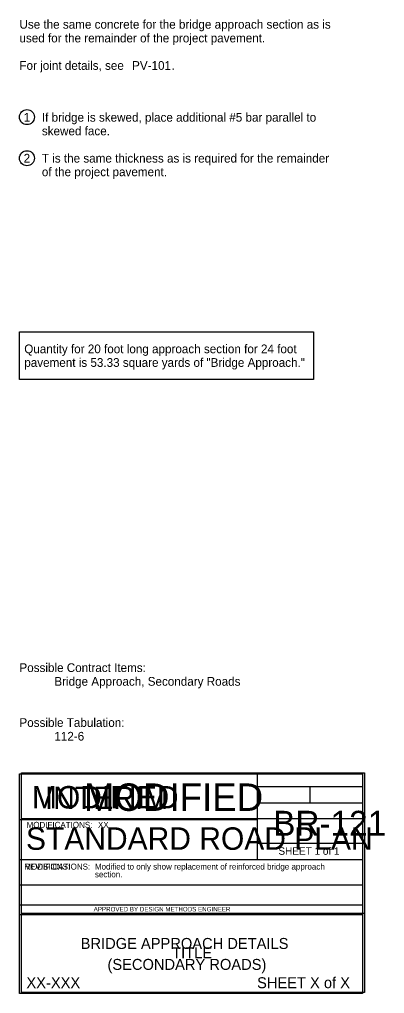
# Model space of a CAD drawing. Extents: x -2134222 to -2124595, y -2139046 to -2134021.
# Drawn here: x -2132487 to -2131755, y -2139046 to -2137094 of the extents above; entities that cross this region are included whole.
import ezdxf

# ---------------------------------------------------------------- set-up
doc = ezdxf.new("R2010")
doc.units = 0
for name, color, linetype in [('Barrier', 7, 'Continuous'), ('BridgeSuperStructureExisting', 7, 'Continuous'), ('Dimension', 7, 'Continuous'), ('dsnAlignmentCurveData', 7, 'Continuous'), ('dsnAlignmentTic', 7, 'Continuous'), ('DsnShtInsideBorder', 7, 'Continuous'), ('DsnShtPlotIdentification', 7, 'Continuous'), ('dsnStdLabel', 7, 'Continuous')]:
    doc.layers.add(name, color=color, linetype=linetype)

msp = doc.modelspace()

# ---------------------------------------------------------------- linework, layer by layer
at = {"layer": 'BridgeSuperStructureExisting'}
msp.add_lwpolyline([(-2132487.5, -2137719.6), (-2131897.5, -2137719.6), (-2131897.5, -2137815.6), (-2132487.5, -2137815.6)], close=True, dxfattribs=at)
for centre in [(-2132472.5, -2137289.5), (-2132472.5, -2137371.8)]:
    msp.add_circle(centre, 15, dxfattribs=at)
at = {"layer": 'Dimension'}
for p, q in [((-2132010.4, -2138605.9), (-2132010.4, -2138697.3)), ((-2132010.4, -2138630.9), (-2131799.4, -2138630.9)), ((-2131904.9, -2138630.9), (-2131904.9, -2138664.1)), ((-2132010.4, -2138664.1), (-2131799.4, -2138664.1)), ((-2132487.5, -2138697.3), (-2132010.4, -2138697.3)), ((-2132010.4, -2138697.3), (-2132010.4, -2138777.3)), ((-2131799.4, -2138745.1), (-2132010.4, -2138745.1)), ((-2132487.5, -2138777.3), (-2131799.4, -2138777.3)), ((-2132487.5, -2138828.3), (-2131799.4, -2138828.3)), ((-2132487.5, -2138868.3), (-2131799.4, -2138868.3)), ((-2132487.5, -2138887.3), (-2131799.4, -2138887.3))]:
    msp.add_line(p, q, dxfattribs=at)
msp.add_lwpolyline([(-2132487.5, -2138605.9), (-2131799.4, -2138605.9), (-2131799.4, -2139045.9), (-2132487.5, -2139045.9)], close=True, dxfattribs=at)
at = {"layer": 'DsnShtInsideBorder'}
for p, q in [((-2132483.1, -2138695), (-2131795.1, -2138695)), ((-2132483.1, -2138885), (-2131795.1, -2138885))]:
    msp.add_line(p, q, dxfattribs=at)
msp.add_lwpolyline([(-2132483.1, -2138603.7), (-2131795.1, -2138603.7), (-2131795.1, -2139043.7), (-2132483.1, -2139043.7)], close=True, dxfattribs=at)

# ---------------------------------------------------------------- texts
at = {"layer": 'Barrier'}
for s, p in [('1', (-2132479, -2137298.6)), ('If bridge is skewed, place additional #5 bar parallel to ', (-2132442.5, -2137298.6)), ('skewed face.', (-2132442.5, -2137325.9)), ('2', (-2132479, -2137380.6)), ('T is the same thickness as is required for the remainder ', (-2132442.5, -2137380.6)), ('of the project pavement.', (-2132442.5, -2137407.9))]:
    msp.add_text(s, height=17.5, dxfattribs=at).set_placement(p)
at = {"layer": 'Dimension'}
for s, height, p in [('BR-121', 50, (-2131978.5, -2138729.8)), ('STANDARD ROAD PLAN', 45.001, (-2132474.4, -2138757.9)), ('SHEET 1 of 1', 15, (-2131968, -2138767.9)), ('Modified to only show replacement of reinforced bridge approach ', 12, (-2132336.1, -2138797.5)), ('section.', 12, (-2132336.1, -2138813.1)), ('APPROVED BY DESIGN METHODS ENGINEER', 9.003, (-2132338.5, -2138881.4)), ('BRIDGE APPROACH DETAILS', 22, (-2132364.7, -2138956.6)), ('(SECONDARY ROADS)', 22, (-2132310.9, -2138998.6))]:
    msp.add_text(s, height=height, dxfattribs=at).set_placement(p)
at = {"layer": 'dsnAlignmentCurveData'}
msp.add_text('REVISIONS:', height=12, dxfattribs=at).set_placement((-2132477.5, -2138797.6))
at = {"layer": 'dsnAlignmentTic'}
for s, height, p in [('MODIFIED', 45, (-2132462.4, -2138675.1)), ('MODIFICATIONS:', 12, (-2132477.5, -2138797.6))]:
    msp.add_text(s, height=height, dxfattribs=at).set_placement(p)
at = {"layer": 'DsnShtInsideBorder'}
for s, height, p in [('MODIFIED', 55, (-2132358.1, -2138679.9)), ('MODIFICATIONS:', 12, (-2132473.1, -2138713.9)), ('XX', 12, (-2132329.9, -2138713.9)), ('TITLE', 22, (-2132181.1, -2138975.4)), ('XX-XXX', 22, (-2132473.5, -2139035.3)), ('SHEET X of X', 22, (-2132010.8, -2139035.3))]:
    msp.add_text(s, height=height, dxfattribs=at).set_placement(p)
at = {"layer": 'DsnShtPlotIdentification'}
msp.add_text('INTERIM', height=45, dxfattribs=at).set_placement((-2132436.5, -2138676.3))
at = {"layer": 'dsnStdLabel'}
for s, p in [('Use the same concrete for the bridge approach section as is ', (-2132487.5, -2137112.2)), ('used for the remainder of the project pavement.', (-2132487.5, -2137139.7)), ('For joint details, see ', (-2132487.5, -2137194.7)), ('PV-101', (-2132261.5, -2137194.7)), ('PV-101', (-2132261.5, -2137194.7)), ('.', (-2132182.2, -2137194.7)), ('Quantity for 20 foot long approach section for 24 foot', (-2132477.8, -2137762.7)), ('pavement is 53.33 square yards of "Bridge Approach."', (-2132477.8, -2137790)), ('Possible Contract Items:', (-2132487.5, -2138401.6)), ('Bridge Approach, Secondary Roads', (-2132417.5, -2138429.1)), ('Possible Tabulation:  ', (-2132487.5, -2138511.6)), ('112-6', (-2132417.5, -2138539.1)), ('112-6', (-2132417.5, -2138539.1))]:
    msp.add_text(s, height=17.5, dxfattribs=at).set_placement(p)

doc.saveas('drawing.dxf')
